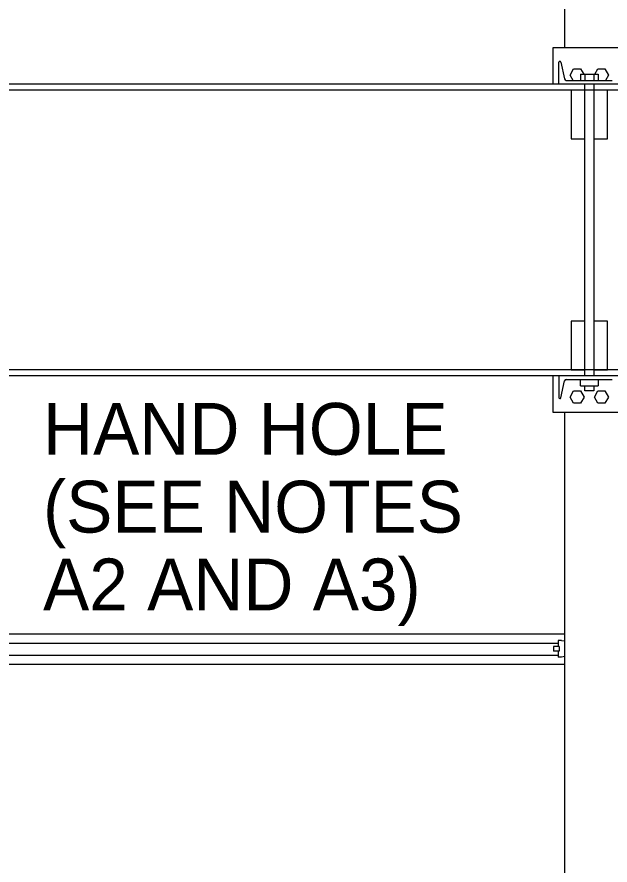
# Model space of a CAD drawing. Extents: x 99862 to 103680, y 99470 to 105076.
# Drawn here: x 100958.3 to 101141.3, y 101388.9 to 101650.6 of the extents above; entities that cross this region are included whole.
import ezdxf

# ---------------------------------------------------------------- set-up
doc = ezdxf.new("R2010")
doc.units = 0
for name, color, linetype in [('Level 10', 7, 'Continuous'), ('Level 12', 7, 'Continuous'), ('Level 19', 7, 'Continuous'), ('Level 2', 7, 'Continuous'), ('Level 20', 7, 'Continuous'), ('Level 9', 7, 'Continuous')]:
    doc.layers.add(name, color=color, linetype=linetype)

msp = doc.modelspace()

# ---------------------------------------------------------------- linework, layer by layer
at = {"layer": 'Level 10'}
for p, q in [((101123.67, 101641.07), (101123.67, 101629.82)), ((101146.16, 101641.07), (101123.67, 101641.07)), ((101125.55, 101629.82), (101125.55, 101636.58)), ((101126.1, 101636.65), (101127.28, 101631.42)), ((101144.29, 101629.82), (101125.55, 101629.82)), ((101127.81, 101630.99), (101142.02, 101630.99)), ((101136.32, 101612.95), (101140.54, 101612.95)), ((101136.32, 101541.73), (101140.54, 101541.73)), ((101123.67, 101539.86), (101123.67, 101528.62)), ((101125.55, 101539.86), (101125.55, 101533.1)), ((101144.29, 101539.86), (101125.55, 101539.86)), ((101126.1, 101533.04), (101127.28, 101538.27)), ((101127.81, 101538.69), (101142.02, 101538.69)), ((101123.67, 101528.62), (101146.16, 101528.62))]:
    msp.add_line(p, q, dxfattribs=at)
for points in [[(101133.51, 101627.95), (101129.29, 101627.95), (101129.29, 101612.95), (101133.51, 101612.95)], [(101140.54, 101612.95), (101140.54, 101627.95), (101136.32, 101627.95)], [(101133.51, 101556.73), (101129.29, 101556.73), (101129.29, 101541.73), (101133.51, 101541.73)], [(101140.54, 101541.73), (101140.54, 101556.73), (101136.32, 101556.73)]]:
    msp.add_lwpolyline(points, dxfattribs=at)
for centre, radius, start, end in [((101125.83, 101636.58), 0.281, 12.739, 180), ((101127.81, 101631.54), 0.544, 192.739, 270), ((101127.81, 101538.15), 0.544, 90, 167.261), ((101125.83, 101533.1), 0.281, 180, 347.261)]:
    msp.add_arc(centre, radius, start, end, dxfattribs=at)
at = {"layer": 'Level 12'}
for p, q in [((101646.35, 101629.82), (100274.6, 101629.82)), ((101646.35, 101627.95), (100276.47, 101627.95)), ((101646.35, 101541.73), (100340.2, 101541.73)), ((101646.35, 101539.86), (100342.07, 101539.86))]:
    msp.add_line(p, q, dxfattribs=at)
at = {"layer": 'Level 19'}
for p, q in [((100928.75, 101460.22), (101127.45, 101460.22)), ((100930.82, 101457.41), (101125.36, 101457.41)), ((101125.35, 101458.22), (101125.34, 101458.22)), ((101125.35, 101458.22), (101125.35, 101456.39)), ((101125.69, 101458.22), (101125.35, 101458.22)), ((101126.35, 101458.22), (101125.69, 101458.22)), ((101126.35, 101458.22), (101127.42, 101458.05)), ((101123.89, 101456.39), (101123.89, 101456.28)), ((101124.1, 101456.39), (101123.89, 101456.39)), ((101123.89, 101456.28), (101123.89, 101454.9)), ((101124.1, 101454.9), (101123.89, 101454.9)), ((101125.6, 101456.39), (101124.1, 101456.39)), ((101125.6, 101454.9), (101124.1, 101454.9)), ((101125.35, 101454.9), (101125.35, 101453.07)), ((101125.6, 101456.39), (101125.6, 101454.9)), ((100930.82, 101453.66), (101125.36, 101453.66)), ((101125.35, 101453.07), (101125.34, 101453.07)), ((101125.69, 101453.07), (101125.35, 101453.07)), ((101126.35, 101453.07), (101125.69, 101453.07)), ((101127.42, 101453.24), (101126.35, 101453.07)), ((100928.75, 101450.85), (101127.45, 101450.85))]:
    msp.add_line(p, q, dxfattribs=at)
at = {"layer": 'Level 2'}
for p, q in [((101127.42, 101641.07), (101127.42, 101744.85)), ((101127.42, 101322.45), (101127.42, 101528.62))]:
    msp.add_line(p, q, dxfattribs=at)
at = {"layer": 'Level 9'}
for p, q in [((101129, 101632.63), (101130.09, 101634.51)), ((101129.95, 101630.99), (101129, 101632.63)), ((101130.09, 101634.51), (101132.25, 101634.51)), ((101132.21, 101632.87), (101133.56, 101632.87)), ((101132.21, 101632.87), (101132.21, 101630.99)), ((101132.25, 101634.51), (101133.2, 101632.87)), ((101133.56, 101632.87), (101133.56, 101630.99)), ((101133.56, 101632.87), (101136.27, 101632.87)), ((101136.27, 101632.87), (101137.62, 101632.87)), ((101136.27, 101632.87), (101136.27, 101630.99)), ((101136.64, 101632.87), (101137.58, 101634.51)), ((101137.58, 101634.51), (101139.75, 101634.51)), ((101137.62, 101632.87), (101137.62, 101630.99)), ((101139.75, 101634.51), (101140.83, 101632.63)), ((101140.83, 101632.63), (101139.88, 101630.99)), ((101133.51, 101539.86), (101133.51, 101629.82)), ((101136.32, 101629.82), (101136.32, 101539.86)), ((101132.21, 101536.77), (101132.21, 101538.64)), ((101137.62, 101538.64), (101137.62, 101536.77)), ((101132.21, 101536.77), (101133.56, 101536.77)), ((101133.51, 101535.23), (101133.51, 101536.77)), ((101136.32, 101535.23), (101133.51, 101535.23)), ((101136.32, 101536.77), (101136.32, 101535.23)), ((101129, 101533.3), (101130.09, 101535.17)), ((101130.09, 101531.43), (101129, 101533.3)), ((101130.09, 101535.17), (101132.25, 101535.17)), ((101132.25, 101535.17), (101133.33, 101533.3)), ((101133.33, 101533.3), (101132.25, 101531.43)), ((101136.5, 101533.3), (101137.58, 101535.17)), ((101137.58, 101531.43), (101136.5, 101533.3)), ((101137.58, 101535.17), (101139.75, 101535.17)), ((101139.75, 101535.17), (101140.83, 101533.3)), ((101140.83, 101533.3), (101139.75, 101531.43)), ((101132.25, 101531.43), (101130.09, 101531.43)), ((101139.75, 101531.43), (101137.58, 101531.43))]:
    msp.add_line(p, q, dxfattribs=at)
msp.add_lwpolyline([(101133.56, 101536.77), (101136.27, 101536.77), (101137.62, 101536.77)], dxfattribs=at)

# ---------------------------------------------------------------- texts
at = {"layer": 'Level 20'}
for s, p in [('HAND HOLE', (100966.35, 101515.49)), ('(SEE NOTES', (100966.35, 101491.49)), ('A2 AND A3)', (100966.35, 101467.49))]:
    msp.add_text(s, height=16, dxfattribs=at).set_placement(p)

doc.saveas('drawing.dxf')
